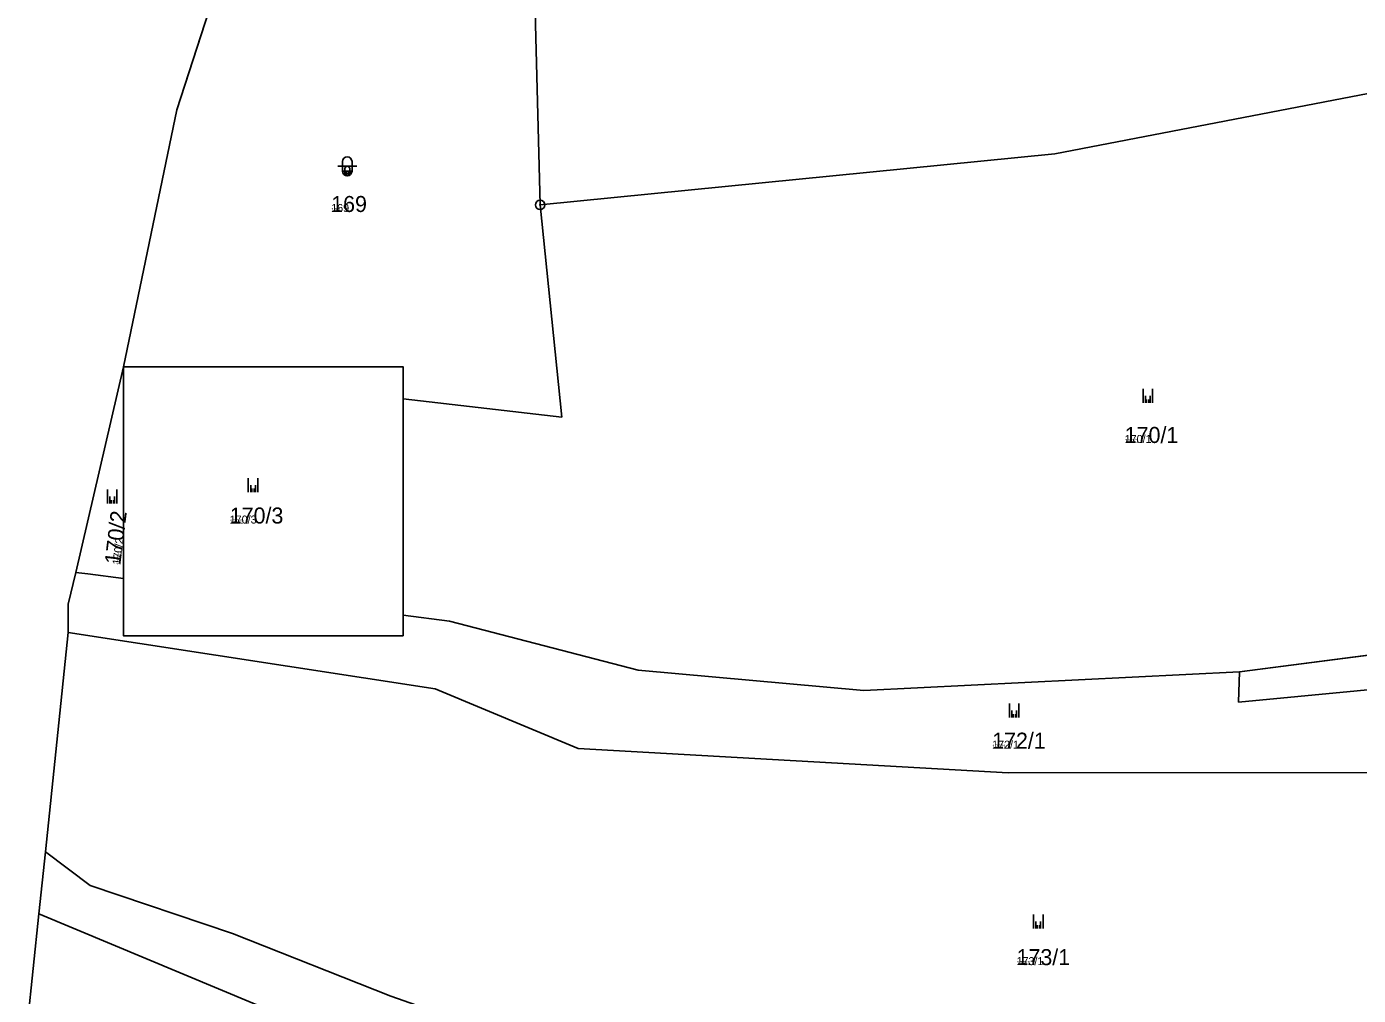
# Model space of a CAD drawing. Extents: x -759873 to -758487, y -975024 to -973516.
# Drawn here: x -759747.2 to -759605.8, y -974577.8 to -974475 of the extents above; entities that cross this region are included whole.
import ezdxf

# ---------------------------------------------------------------- set-up
doc = ezdxf.new("R2010")
doc.units = 0
for name, color, linetype in [('KAT_01_hranice KU', 7, 'Continuous'), ('KAT_02_hranice parcel', 7, 'Continuous'), ('KAT_03_1000_čísla parcelní', 7, 'Continuous'), ('KAT_03_250_čísla parcelní', 7, 'Continuous'), ('KAT_03_500_čísla parcelní', 7, 'Continuous'), ('KAT_05_1000_značky kultur', 7, 'Continuous'), ('KAT_05_250_značky kultur', 7, 'Continuous'), ('KAT_05_500_značky kultur', 7, 'Continuous'), ('KAT_11_značky bodu BP', 7, 'Continuous'), ('KAT_14_plocha_pozemek', 7, 'Continuous')]:
    doc.layers.add(name, color=color, linetype=linetype)

msp = doc.modelspace()

# ---------------------------------------------------------------- linework, layer by layer
at = {"layer": 'KAT_01_hranice KU'}
msp.add_lwpolyline([(-759725.75, -974466.86), (-759731.24, -974483.81), (-759736.9, -974511.06), (-759741.97, -974532.88), (-759742.76, -974536.26), (-759742.76, -974539.26), (-759745.19, -974562.55), (-759745.87, -974569.1), (-759747.08, -974580.72)], dxfattribs=at)
at = {"layer": 'KAT_02_hranice parcel'}
for p, q in [((-759731.24, -974483.81), (-759725.75, -974466.86)), ((-759736.9, -974511.06), (-759731.24, -974483.81)), ((-759741.97, -974532.88), (-759736.9, -974511.06)), ((-759736.9, -974533.54), (-759736.9, -974511.06)), ((-759707.2, -974514.47), (-759707.2, -974537.43)), ((-759742.76, -974536.26), (-759741.97, -974532.88)), ((-759742.76, -974539.26), (-759742.76, -974536.26)), ((-759745.19, -974562.55), (-759742.76, -974539.26)), ((-759618.38, -974543.43), (-759586.31, -974539.3)), ((-759745.87, -974569.1), (-759745.19, -974562.55))]:
    msp.add_line(p, q, dxfattribs=at)
for points in [[(-759564.02, -974464.22), (-759597.03, -974480.57), (-759638.01, -974488.47), (-759692.66, -974493.88)], [(-759692.66, -974493.88), (-759693.21, -974471.97), (-759715.67, -974471.76), (-759725.75, -974466.86)], [(-759707.2, -974514.47), (-759690.36, -974516.4), (-759692.66, -974493.88)], [(-759736.9, -974511.06), (-759707.2, -974511.06), (-759707.2, -974514.47)], [(-759741.97, -974532.88), (-759740.69, -974533.05), (-759736.9, -974533.54)], [(-759736.9, -974533.54), (-759736.9, -974539.6), (-759707.2, -974539.6), (-759707.2, -974537.43)], [(-759707.2, -974537.43), (-759702.28, -974538.07), (-759682.23, -974543.26), (-759658.27, -974545.43), (-759618.38, -974543.43)], [(-759618.38, -974543.43), (-759618.49, -974546.65), (-759586.25, -974543.56), (-759551.11, -974538.1), (-759540.14, -974539.55), (-759513.11, -974546.21)], [(-759742.76, -974539.26), (-759703.8, -974545.25), (-759688.61, -974551.58), (-759642.97, -974554.16), (-759564.84, -974554.11), (-759563.58, -974549.84), (-759551.48, -974544.27), (-759550.22, -974544.33)], [(-759745.19, -974562.55), (-759740.43, -974566.11), (-759725.32, -974571.2), (-759708.52, -974577.87), (-759697.61, -974581.66), (-759664.15, -974586.53), (-759642.54, -974589.75), (-759622.82, -974591), (-759601.22, -974591.07), (-759588.97, -974591.35), (-759580.29, -974589.86), (-759566.46, -974586.39), (-759552.88, -974583.63), (-759547.64, -974583.57)], [(-759747.18, -974581.65), (-759747.14, -974581.27), (-759747.08, -974580.72), (-759745.87, -974569.1)], [(-759745.87, -974569.1), (-759700, -974588.25), (-759649.5, -974597.3), (-759602.4, -974597), (-759547.6, -974592.2), (-759547.08, -974592.24)]]:
    msp.add_lwpolyline(points, dxfattribs=at)
at = {"layer": 'KAT_05_1000_značky kultur'}
for p, q in [((-759714.13, -974489.79), (-759712.13, -974489.79)), ((-759713.63, -974489.29), (-759713.63, -974490.29)), ((-759712.63, -974490.29), (-759712.63, -974489.29)), ((-759628.64, -974514.89), (-759628.64, -974513.39)), ((-759627.64, -974514.89), (-759627.64, -974513.39)), ((-759723.64, -974524.37), (-759723.64, -974522.87)), ((-759722.64, -974524.37), (-759722.64, -974522.87)), ((-759738.6, -974525.58), (-759738.6, -974524.08)), ((-759737.6, -974525.58), (-759737.6, -974524.08)), ((-759642.81, -974548.28), (-759642.81, -974546.78)), ((-759641.81, -974548.28), (-759641.81, -974546.78)), ((-759640.26, -974570.68), (-759640.26, -974569.18)), ((-759639.26, -974570.68), (-759639.26, -974569.18))]:
    msp.add_line(p, q, dxfattribs=at)
for centre, start, end in [((-759713.13, -974489.29), 0, 180), ((-759713.13, -974490.29), 180, 359.9879)]:
    msp.add_arc(centre, 0.5, start, end, dxfattribs=at)
at = {"layer": 'KAT_05_250_značky kultur'}
for p, q in [((-759713.38, -974490.54), (-759712.88, -974490.54)), ((-759713.26, -974490.42), (-759713.26, -974490.67)), ((-759713, -974490.67), (-759713, -974490.42)), ((-759628.26, -974514.89), (-759628.26, -974514.52)), ((-759628.01, -974514.89), (-759628.01, -974514.52)), ((-759723.26, -974524.37), (-759723.26, -974523.99)), ((-759723.01, -974524.37), (-759723.01, -974523.99)), ((-759738.22, -974525.58), (-759738.22, -974525.21)), ((-759737.97, -974525.58), (-759737.97, -974525.21)), ((-759642.43, -974548.28), (-759642.43, -974547.91)), ((-759642.18, -974548.28), (-759642.18, -974547.91)), ((-759639.88, -974570.68), (-759639.88, -974570.31)), ((-759639.63, -974570.68), (-759639.63, -974570.31))]:
    msp.add_line(p, q, dxfattribs=at)
for centre, start, end in [((-759713.13, -974490.42), 0, 180), ((-759713.13, -974490.67), 180, 359.9879)]:
    msp.add_arc(centre, 0.125, start, end, dxfattribs=at)
at = {"layer": 'KAT_05_500_značky kultur'}
for p, q in [((-759713.38, -974490.04), (-759713.38, -974490.54)), ((-759712.88, -974490.54), (-759712.88, -974490.04)), ((-759713.63, -974490.29), (-759712.63, -974490.29)), ((-759628.39, -974514.89), (-759628.39, -974514.14)), ((-759627.89, -974514.89), (-759627.89, -974514.14)), ((-759723.39, -974524.37), (-759723.39, -974523.62)), ((-759722.89, -974524.37), (-759722.89, -974523.62)), ((-759738.35, -974525.58), (-759738.35, -974524.83)), ((-759737.84, -974525.58), (-759737.84, -974524.83)), ((-759642.56, -974548.28), (-759642.56, -974547.53)), ((-759642.06, -974548.28), (-759642.06, -974547.53)), ((-759640.01, -974570.68), (-759640.01, -974569.93)), ((-759639.51, -974570.68), (-759639.51, -974569.93))]:
    msp.add_line(p, q, dxfattribs=at)
for centre, start, end in [((-759713.13, -974490.04), 0, 180), ((-759713.13, -974490.54), 180, 359.9879)]:
    msp.add_arc(centre, 0.25, start, end, dxfattribs=at)
at = {"layer": 'KAT_11_značky bodu BP'}
for radius in [0.5, 0.0303]:
    msp.add_circle((-759692.66, -974493.88), radius, dxfattribs=at)
at = {"layer": 'KAT_14_plocha_pozemek'}
for points in [[(-759638.01, -974488.47), (-759692.66, -974493.88), (-759690.36, -974516.4), (-759707.2, -974514.47), (-759707.2, -974537.43), (-759702.28, -974538.07), (-759682.23, -974543.26), (-759658.27, -974545.43), (-759618.38, -974543.43), (-759586.31, -974539.3), (-759586.76, -974505.88), (-759530.78, -974491.67), (-759538.67, -974453.48), (-759564.02, -974464.22), (-759597.03, -974480.57)], [(-759693.21, -974471.97), (-759715.67, -974471.76), (-759725.75, -974466.86), (-759731.24, -974483.81), (-759736.9, -974511.06), (-759707.2, -974511.06), (-759707.2, -974514.47), (-759690.36, -974516.4), (-759692.66, -974493.88)], [(-759740.69, -974533.05), (-759736.9, -974533.54), (-759736.9, -974511.06), (-759741.97, -974532.88)], [(-759707.2, -974539.6), (-759707.2, -974537.43), (-759707.2, -974514.47), (-759707.2, -974511.06), (-759736.9, -974511.06), (-759736.9, -974533.54), (-759736.9, -974539.6)], [(-759601.22, -974591.07), (-759588.97, -974591.35), (-759580.29, -974589.86), (-759566.46, -974586.39), (-759552.88, -974583.63), (-759547.64, -974583.57), (-759550.22, -974544.33), (-759551.48, -974544.27), (-759563.58, -974549.84), (-759564.84, -974554.11), (-759642.97, -974554.16), (-759688.61, -974551.58), (-759703.8, -974545.25), (-759742.76, -974539.26), (-759745.19, -974562.55), (-759740.43, -974566.11), (-759725.32, -974571.2), (-759708.52, -974577.87), (-759697.61, -974581.66), (-759664.15, -974586.53), (-759642.54, -974589.75), (-759622.82, -974591)], [(-759547.08, -974592.24), (-759547.64, -974583.57), (-759552.88, -974583.63), (-759566.46, -974586.39), (-759580.29, -974589.86), (-759588.97, -974591.35), (-759601.22, -974591.07), (-759622.82, -974591), (-759642.54, -974589.75), (-759664.15, -974586.53), (-759697.61, -974581.66), (-759708.52, -974577.87), (-759725.32, -974571.2), (-759740.43, -974566.11), (-759745.19, -974562.55), (-759745.87, -974569.1), (-759700, -974588.25), (-759649.5, -974597.3), (-759602.4, -974597), (-759547.6, -974592.2)]]:
    msp.add_lwpolyline(points, close=True, dxfattribs=at)
for points in [[(-759693.21, -974471.97), (-759692.66, -974493.88), (-759638.01, -974488.47), (-759597.03, -974480.57), (-759564.02, -974464.22)], [(-759586.25, -974543.56), (-759618.49, -974546.65), (-759618.38, -974543.43), (-759658.27, -974545.43), (-759682.23, -974543.26), (-759702.28, -974538.07), (-759707.2, -974537.43), (-759707.2, -974539.6), (-759736.9, -974539.6), (-759736.9, -974533.54), (-759740.69, -974533.05), (-759741.97, -974532.88), (-759742.76, -974536.26), (-759742.76, -974539.26), (-759703.8, -974545.25), (-759688.61, -974551.58), (-759642.97, -974554.16), (-759564.84, -974554.11)], [(-759456.43, -974541.94), (-759462.56, -974542.46), (-759503.24, -974543.85), (-759511.54, -974542.81), (-759526.67, -974537.22), (-759538.42, -974534.77), (-759550.09, -974534.21), (-759586.31, -974539.3), (-759618.38, -974543.43), (-759618.49, -974546.65), (-759586.25, -974543.56), (-759551.11, -974538.1), (-759540.14, -974539.55), (-759513.11, -974546.21), (-759480.52, -974547.43), (-759461.67, -974545.71), (-759455.54, -974548.17)], [(-759700, -974588.25), (-759745.87, -974569.1), (-759747.08, -974580.72)]]:
    msp.add_lwpolyline(points, dxfattribs=at)

# ---------------------------------------------------------------- texts
at = {"layer": 'KAT_03_1000_čísla parcelní'}
for s, p in [('169', (-759714.84, -974494.64)), ('170/1', (-759630.58, -974519.15)), ('170/3', (-759725.61, -974527.7)), ('172/1', (-759644.66, -974551.59)), ('173/1', (-759642.07, -974574.56))]:
    msp.add_text(s, height=1.7, dxfattribs=at).set_placement(p)
msp.add_text('170/2', height=1.7, rotation=83, dxfattribs=at).set_placement((-759737.23, -974532.11))
at = {"layer": 'KAT_03_250_čísla parcelní'}
for s, p in [('169', (-759714.84, -974494.64)), ('170/1', (-759630.58, -974519.15)), ('170/3', (-759725.61, -974527.7)), ('172/1', (-759644.66, -974551.59)), ('173/1', (-759642.07, -974574.56))]:
    msp.add_text(s, height=0.425, dxfattribs=at).set_placement(p)
msp.add_text('170/2', height=0.425, rotation=83, dxfattribs=at).set_placement((-759737.23, -974532.11))
at = {"layer": 'KAT_03_500_čísla parcelní'}
for s, p in [('169', (-759714.84, -974494.64)), ('170/1', (-759630.58, -974519.15)), ('170/3', (-759725.61, -974527.7)), ('172/1', (-759644.66, -974551.59)), ('173/1', (-759642.07, -974574.56))]:
    msp.add_text(s, height=0.85, dxfattribs=at).set_placement(p)
msp.add_text('170/2', height=0.85, rotation=83, dxfattribs=at).set_placement((-759737.23, -974532.11))

doc.saveas('drawing.dxf')
